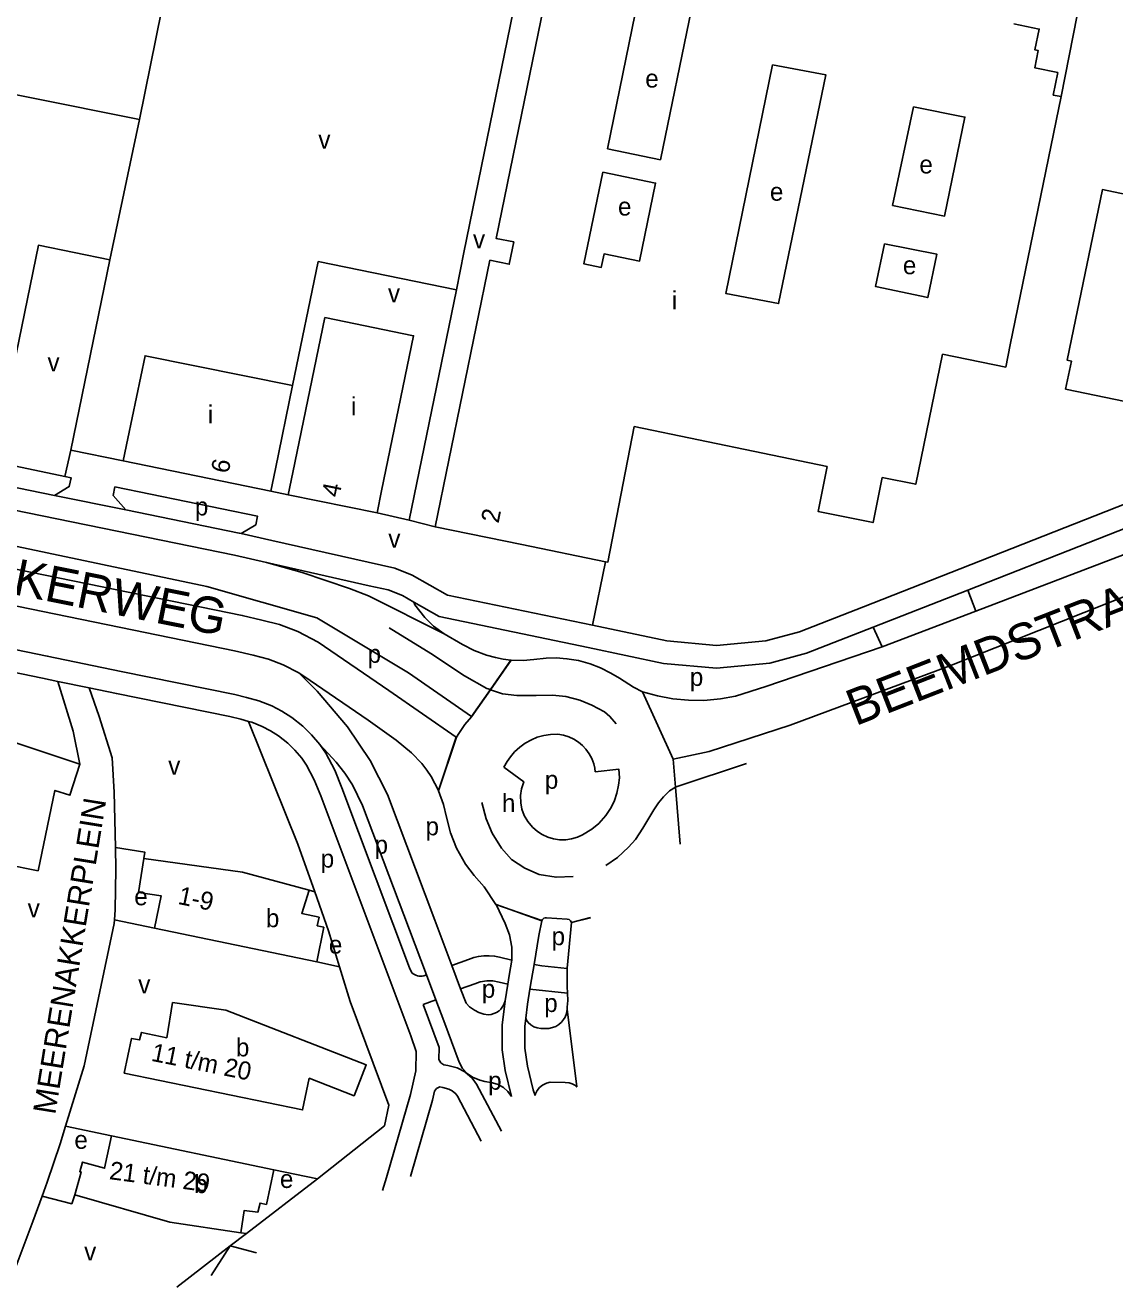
# Model space of a CAD drawing. Extents: x 157699 to 159683, y 381451 to 383293.
# Drawn here: x 158727.7 to 158968.6, y 381916.9 to 382195.6 of the extents above; entities that cross this region are included whole.
import ezdxf

# ---------------------------------------------------------------- set-up
doc = ezdxf.new("R2010")
doc.units = 0
for name, color, linetype in [('BLT_Basislijn', 7, 'Continuous'), ('BLT_Bebouwing', 7, 'Continuous'), ('BLT_Centroide', 7, 'Continuous'), ('BLT_Huisnummer', 7, 'Continuous'), ('BLT_Huisnummer_reeks', 7, 'Continuous'), ('BLT_Onderverdeling_panden', 7, 'Continuous'), ('BLT_Straatnaam', 7, 'Continuous'), ('BLT_Straatnaam_hoofdweg', 7, 'Continuous'), ('BLT_Vlakafsluiter', 7, 'Continuous')]:
    doc.layers.add(name, color=color, linetype=linetype)

msp = doc.modelspace()

# ---------------------------------------------------------------- linework, layer by layer
at = {"layer": 'BLT_Basislijn'}
for p, q in [((158824.7, 382145.3), (158838.81, 382214.57)), ((158823.02, 382137.08), (158824.7, 382145.3)), ((158746.41, 382143.69), (158737.77, 382101.61)), ((158786.8, 382115.91), (158792.49, 382143.37)), ((158792.49, 382143.37), (158823.02, 382137.08)), ((158823.02, 382137.08), (158812.59, 382086.17)), ((158737.77, 382101.61), (158749.36, 382099.29)), ((158720.79, 382099.1), (158736.46, 382095.81)), ((158782, 382092.58), (158785.86, 382091.78)), ((158805.49, 382087.74), (158812.59, 382086.17)), ((158812.59, 382086.17), (158818.34, 382084.7)), ((158936.12, 382070.68), (158937.86, 382066.01)), ((158915.13, 382062.5), (158917.18, 382058.12)), ((158777.07, 382041.68), (158787.99, 382014.51)), ((158790.45, 382004.33), (158791.7, 382003.99)), ((158756.27, 381995.96), (158747.43, 381997.8)), ((158842.96, 381998.23), (158847.5, 381997.99)), ((158792.15, 381988.49), (158797.18, 381987.44)), ((158822.04, 381987.7), (158823.96, 381982.58)), ((158839.29, 381982.51), (158847.6, 381981.63)), ((158799.55, 381979.75), (158808.09, 381956.86)), ((158808.09, 381956.86), (158807.12, 381952.29)), ((158746.77, 381950.06), (158736.65, 381952.18)), ((158807.12, 381952.29), (158792.35, 381940.53)), ((158782.64, 381942.56), (158792.35, 381940.53)), ((158792.35, 381940.53), (158776.63, 381928.47)), ((158776.63, 381928.47), (158773.05, 381925.73)), ((158775.39, 381928.65), (158776.63, 381928.47)), ((158773.05, 381925.73), (158761.2, 381916.64)), ((158773.05, 381925.73), (158778.84, 381924.16))]:
    msp.add_line(p, q, dxfattribs=at)
for points in [[(158898.79, 382234.19), (158899.9, 382239.98), (158900.48, 382240.17), (158965.55, 382226.62), (158965.66, 382225.18), (158956.72, 382179.78)], [(158870.97, 382033.32), (158878.88, 382035.05), (158896.8, 382040.83), (158932.11, 382053.92), (159006.54, 382083.5), (159037.22, 382098.8), (159129.65, 382150.55), (159151.52, 382167.42), (159185.85, 382195.18)], [(159089.91, 382150.02), (159088.85, 382149.22), (159035.79, 382119.61), (159022.43, 382112.48), (159008.87, 382105.74), (158998.17, 382100.87), (158987.38, 382096.23), (158934.38, 382075.37)], [(158544.73, 382122.06), (158548.84, 382121.35), (158552.02, 382120.93), (158587.89, 382116.66), (158592.01, 382115.79), (158605.12, 382111.75), (158611.85, 382110.66), (158626.88, 382108.26), (158640.25, 382105.79), (158773.96, 382078.4), (158781.03, 382076.78)], [(159042.78, 382117.78), (159038.18, 382115.22), (159024.72, 382108.03), (159011.02, 382101.22), (159000.2, 382096.29), (158989.28, 382091.61), (158936.12, 382070.68)], [(158937.86, 382066.01), (158978.78, 382081.64), (158996.94, 382088.82), (159013.88, 382096.22), (159030.16, 382104.6), (159045.4, 382113.11)], [(158672.43, 382104.3), (158734.22, 382091.64)], [(158737.77, 382101.61), (158736.46, 382095.81)], [(158603.4, 382100.5), (158713.37, 382077.85), (158775.69, 382065.11), (158780, 382064.08), (158783.9, 382063.08), (158788, 382061.52), (158792.49, 382059.17)], [(158826.34, 382042.72), (158812.46, 382052.4), (158792.15, 382064.6), (158767.88, 382071.47), (158640.23, 382098.41), (158603.4, 382100.5)], [(158585.04, 382095.72), (158600.84, 382092.86), (158711.76, 382070.02), (158773.96, 382057.3), (158778.07, 382056.31), (158781.48, 382055.44), (158784.72, 382054.21), (158788.18, 382052.4)], [(158736.46, 382095.81), (158737.88, 382095.51), (158737.46, 382093.59), (158734.22, 382091.64)], [(158749.92, 382088.43), (158747.16, 382091.59), (158747.56, 382093.49), (158779.09, 382087.01), (158778.69, 382085.11), (158775.47, 382083.18)], [(158734.22, 382091.64), (158749.92, 382088.43)], [(158749.92, 382088.43), (158775.02, 382083.29), (158775.47, 382083.18)], [(158600.15, 382083.33), (158656.15, 382071.8), (158694.96, 382063.83), (158732.57, 382056.1), (158748.9, 382052.72), (158774.02, 382047.61), (158776.64, 382046.99), (158779.39, 382046.22), (158782.2, 382045.1), (158784.45, 382043.93), (158786.62, 382042.54), (158789.07, 382040.6), (158791.02, 382038.68), (158792.82, 382036.54)], [(158775.47, 382083.18), (158782.26, 382081.63)], [(158853.15, 382062.93), (158821.03, 382069.59), (158813.27, 382074.02), (158809.39, 382075.53), (158782.26, 382081.63)], [(158803.78, 382071.67), (158781.03, 382076.78)], [(158853.15, 382062.93), (158856.02, 382076.98)], [(158934.38, 382075.37), (158913.01, 382067.03)], [(158813.62, 382068.06), (158811.11, 382069.49), (158807.92, 382070.74), (158803.78, 382071.67)], [(158936.12, 382070.68), (158915.13, 382062.5)], [(158852.13, 382058.04), (158819.24, 382064.86), (158813.62, 382068.06)], [(158813.62, 382068.06), (158813.82, 382067.47), (158816.03, 382064.61), (158817.96, 382062.7), (158820.3, 382061.05)], [(158913.01, 382067.03), (158898.86, 382061.48), (158891.46, 382059.48), (158880.51, 382058.47), (158869.56, 382059.46), (158853.15, 382062.93)], [(158917.18, 382058.12), (158937.86, 382066.01)], [(158669.58, 382063.94), (158693.96, 382058.93), (158731.56, 382051.2), (158734.95, 382050.5)], [(158830.54, 382048.7), (158829.77, 382048.96), (158824.83, 382051.76), (158817.41, 382056.65), (158808.18, 382062.32)], [(158915.13, 382062.5), (158900.43, 382056.73), (158892.35, 382054.54), (158880.51, 382053.45), (158868.82, 382054.5), (158852.13, 382058.04)], [(158792.49, 382059.17), (158808.07, 382048.49), (158823.01, 382038.2)], [(158820.3, 382061.05), (158824.35, 382058.69), (158826.94, 382057.38), (158829.7, 382056.33), (158831.66, 382055.79), (158833.37, 382055.44), (158835.1, 382055.2)], [(158864.18, 382048.21), (158867.46, 382047.29), (158870.88, 382046.66), (158874.32, 382046.33), (158877.75, 382046.31), (158881.4, 382046.63), (158884.72, 382047.23), (158891.42, 382049.39), (158917.18, 382058.12)], [(158835.1, 382055.2), (158835.15, 382055.19)], [(158835.15, 382055.19), (158837.78, 382055.15), (158840.13, 382055.36), (158842.85, 382055.67), (158845.05, 382055.7), (158847.47, 382055.53), (158849.99, 382055.11), (158852.61, 382054.39), (158854.85, 382053.53), (158857.17, 382052.37), (158859.05, 382051.21), (158862.18, 382049.24), (158864.18, 382048.21)], [(158739.81, 382032.19), (158738.33, 382039.52), (158734.95, 382050.5)], [(158734.95, 382050.5), (158741.84, 382049.07)], [(158822.04, 381987.7), (158818.26, 381997.73), (158807.81, 382025.49), (158803.95, 382033.03), (158798.97, 382040.45), (158792.24, 382048.38), (158788.18, 382052.4)], [(158788.18, 382052.4), (158790.74, 382050.68), (158803.49, 382041.93), (158809.68, 382037.53), (158813.14, 382034.71), (158815.36, 382032.37), (158816.5, 382030.9), (158817.45, 382029.48), (158819.07, 382026.39)], [(158741.84, 382049.07), (158744.08, 382042.74), (158746.97, 382033.6), (158747.4, 382026), (158747.66, 382013.78)], [(158741.84, 382049.07), (158747.89, 382047.82), (158772.96, 382042.72), (158775.39, 382042.15), (158777.07, 382041.68)], [(158830.59, 382048.68), (158830.54, 382048.7)], [(158858.35, 382041.12), (158856.96, 382042.78), (158855.74, 382043.78), (158853, 382045.25), (158850.32, 382046.33), (158847.23, 382047.15), (158844.28, 382047.48), (158840.63, 382047.37), (158836.41, 382047.43), (158833.24, 382047.78), (158830.59, 382048.68)], [(158823.05, 382038.17), (158823.54, 382039.03), (158824.93, 382041), (158826.39, 382042.69)], [(158826.39, 382042.69), (158826.34, 382042.72)], [(158777.07, 382041.68), (158777.78, 382041.48), (158780.11, 382040.55), (158781.94, 382039.6), (158783.71, 382038.47), (158785.75, 382036.85), (158787.35, 382035.28), (158788.84, 382033.51), (158789.87, 382032.01), (158791.6, 382028.79), (158793.05, 382025.2), (158812.93, 381972.14)], [(158792.82, 382036.54), (158794.15, 382034.62), (158796.13, 382030.91), (158797.71, 382027.02), (158812.63, 381987.18), (158813.19, 381986.1), (158813.46, 381985.88), (158813.76, 381985.69), (158814.05, 381985.55), (158814.43, 381985.43), (158814.74, 381985.37), (158815.16, 381985.34), (158815.47, 381985.36), (158815.85, 381985.43), (158816.4, 381985.64)], [(158816.4, 381985.64), (158812.64, 381995.61), (158802.29, 382023.1), (158800.07, 382027.64), (158798.39, 382030.26), (158796.44, 382032.69), (158792.82, 382036.54)], [(158823.01, 382038.2), (158823.05, 382038.17)], [(158887.15, 382032.39), (158871.82, 382027.31), (158871.47, 382027.1)], [(158819.07, 382026.39), (158819.1, 382026.32)], [(158819.1, 382026.32), (158820.2, 382023.28), (158820.87, 382020.5), (158821.7, 382017.05), (158823.03, 382013.65), (158825.03, 382010.14), (158826.95, 382007.63), (158829.14, 382005.12), (158831.76, 382001.22)], [(158871.47, 382027.1), (158870.15, 382026.31), (158868.83, 382024.96), (158867.72, 382023.65), (158866.69, 382022.15), (158864.21, 382018.08), (158862.59, 382015.6), (158861.05, 382013.85), (158858.62, 382011.6), (158856.03, 382009.83)], [(158828.62, 382023.77), (158829.63, 382020.11), (158830.95, 382016.98), (158832.98, 382013.68), (158835.24, 382011.14), (158838.17, 382009.22), (158841.32, 382007.86), (158845.05, 382007.22), (158848.86, 382007.41)], [(158791.7, 382003.99), (158787.99, 382014.51)], [(158747.66, 382013.78), (158747.76, 382009.03), (158747.63, 382000), (158747.43, 381997.8)], [(158753.9, 382011.33), (158754.12, 382012.79), (158747.66, 382013.78)], [(158797.18, 381987.44), (158794.74, 381995.37), (158791.7, 382003.99)], [(158831.76, 382001.22), (158831.79, 382001.16)], [(158831.79, 382001.16), (158833.83, 381997.01), (158834.78, 381994.46), (158835.28, 381991.79), (158835.3, 381988.92)], [(158747.43, 381997.8), (158747.35, 381997.01), (158740.74, 381965.53), (158736.65, 381952.18)], [(158841.94, 381997.59), (158841.28, 381994.35), (158840.2, 381987.91)], [(158841.95, 381997.64), (158841.94, 381997.59)], [(158842.96, 381998.23), (158842.64, 381998.24), (158842.34, 381998.14), (158842.08, 381997.91), (158841.95, 381997.64)], [(158848.49, 381997.25), (158848.28, 381997.61), (158847.94, 381997.87), (158847.5, 381997.99)], [(158847.5, 381987.03), (158847.5, 381987.11), (158848.49, 381997.19)], [(158848.49, 381997.19), (158848.49, 381997.25)], [(158822.04, 381987.7), (158825.69, 381989.07), (158826.85, 381989.46), (158827.91, 381989.71), (158829.07, 381989.85), (158830.3, 381989.88), (158831.48, 381989.78), (158832.53, 381989.59), (158835.3, 381988.92)], [(158799.55, 381979.75), (158797.18, 381987.44)], [(158835.3, 381988.92), (158834.72, 381985.48), (158834.4, 381983.57)], [(158840.2, 381987.91), (158839.65, 381984.65), (158839.29, 381982.51)], [(158840.2, 381987.91), (158841.9, 381987.64), (158847.5, 381987.03)], [(158847.6, 381981.63), (158847.52, 381983.06), (158847.5, 381987.03)], [(158818.48, 381980.13), (158816.4, 381985.64)], [(158823.96, 381982.58), (158827.1, 381983.69), (158828.31, 381984.11), (158829.74, 381984.34), (158831.09, 381984.31), (158832.45, 381984.04), (158834.4, 381983.57)], [(158834.4, 381983.57), (158833.79, 381979.89)], [(158833.79, 381979.89), (158833.61, 381979.3), (158833.3, 381978.69), (158832.85, 381978.09), (158832.45, 381977.71), (158831.87, 381977.32), (158831.33, 381977.07), (158830.69, 381976.89), (158830.06, 381976.82), (158829.1, 381976.98), (158827.98, 381977.35), (158827.03, 381977.82), (158825.93, 381978.61), (158825.18, 381979.36), (158823.96, 381982.58)], [(158839.29, 381982.51), (158838.74, 381979.19), (158838.37, 381976.04)], [(158847.68, 381980), (158847.6, 381981.63)], [(158815.72, 381979.06), (158818.48, 381980.13)], [(158815.72, 381979.06), (158819.19, 381969.56)], [(158835.19, 381958.78), (158834.41, 381959.85), (158833.41, 381960.73), (158832.29, 381961.37), (158830.99, 381961.79), (158829.34, 381962.08), (158828.18, 381962.39), (158826.62, 381963), (158825.43, 381963.83), (158824.41, 381964.95), (158823.64, 381966.37), (158820.23, 381975.47), (158818.48, 381980.13)], [(158838.37, 381976.04), (158838.55, 381975.64), (158838.93, 381975.1), (158839.5, 381974.56), (158840.17, 381974.15), (158840.87, 381973.91), (158841.67, 381973.81), (158843.49, 381973.81), (158844.31, 381973.98), (158845, 381974.26), (158845.65, 381974.66), (158846.26, 381975.2), (158846.72, 381975.77), (158847.04, 381976.32), (158847.34, 381977.08), (158847.5, 381978.04)], [(158847.5, 381978.04), (158847.51, 381978.49), (158847.68, 381980)], [(158812.93, 381972.14), (158814.17, 381968.73)], [(158814.17, 381968.73), (158814.08, 381964.4), (158812.88, 381959.2), (158807.58, 381940.83), (158806.68, 381938.01)], [(158819.19, 381969.56), (158819.14, 381966.95), (158819.59, 381966.18)], [(158819.59, 381966.18), (158820.22, 381965.78), (158821.11, 381965.63), (158823.2, 381965.06), (158824.86, 381964.17), (158826.54, 381962.84), (158827.51, 381961.47), (158832.99, 381951.1)], [(158840.44, 381958.99), (158840.51, 381959.32), (158840.89, 381960.09), (158841.43, 381960.77), (158842.08, 381961.29), (158842.92, 381961.7), (158843.77, 381961.89), (158847.06, 381961.87), (158847.93, 381961.77), (158848.59, 381961.56), (158849.19, 381961.23), (158849.6, 381960.92), (158849.64, 381960.89)], [(158818.6, 381960.53), (158818.18, 381959.95), (158817.72, 381957.94), (158812.86, 381941.09)], [(158818.6, 381960.53), (158819.38, 381960.86), (158820.01, 381960.75), (158821.34, 381960.38), (158822.11, 381959.97), (158822.87, 381959.37), (158823.24, 381958.85), (158828.51, 381948.87)], [(158736.65, 381952.18), (158735.47, 381948.31), (158732.54, 381939.79), (158731.44, 381936.75)], [(158731.44, 381936.75), (158729.4, 381931.11), (158724.57, 381918.14)], [(158738.68, 381937.05), (158737.99, 381935.04), (158731.44, 381936.75)], [(158768.8, 381919.17), (158773.05, 381925.73)]]:
    msp.add_lwpolyline(points, dxfattribs=at)
msp.add_lwpolyline([(158833.49, 382031.53), (158834.24, 382032.8), (158834.97, 382033.82), (158835.89, 382034.91), (158837.05, 382035.98), (158838.22, 382036.83), (158839.6, 382037.61), (158840.9, 382038.15), (158842.38, 382038.57), (158843.85, 382038.81), (158845.45, 382038.88), (158846.73, 382038.65), (158847.9, 382038.27), (158848.97, 382037.76), (158850, 382037.11), (158850.9, 382036.35), (158851.67, 382035.53), (158852.41, 382034.5), (158852.97, 382033.47), (158853.42, 382032.27), (158853.66, 382031.32), (158853.74, 382030.53), (158858.91, 382031.14), (158859.06, 382029.23), (158858.89, 382027.56), (158858.52, 382025.82), (158857.96, 382024.15), (158857.24, 382022.62), (158856.1, 382020.87), (158854.52, 382019.12), (158852.96, 382017.84), (158850.87, 382016.61), (158849.78, 382016.1), (158848.48, 382015.71), (158847.24, 382015.52), (158845.81, 382015.52), (158844.51, 382015.71), (158843.24, 382016.09), (158841.97, 382016.69), (158840.97, 382017.36), (158839.83, 382018.31), (158838.82, 382019.51), (158838.02, 382020.89), (158837.51, 382022.29), (158837.24, 382023.65), (158837.21, 382025.29), (158837.44, 382026.74), (158837.97, 382028.3)], close=True, dxfattribs=at)
at = {"layer": 'BLT_Bebouwing'}
for p, q in [((158956.72, 382179.78), (158954.93, 382180.14)), ((158752.99, 382174.76), (158751.5, 382167.79)), ((158751.5, 382167.79), (158746.41, 382143.69)), ((158862.36, 382106.84), (158905, 382098.05)), ((158782, 382092.58), (158749.36, 382099.29)), ((158785.86, 382091.78), (158805.49, 382087.74)), ((158818.34, 382084.7), (158837.5, 382080.81)), ((158837.5, 382080.81), (158856.02, 382076.98))]:
    msp.add_line(p, q, dxfattribs=at)
for points in [[(158760.28, 382210.83), (158752.99, 382174.76)], [(158830.4, 382143.62), (158834.71, 382142.74), (158835.71, 382147.65), (158831.82, 382148.44), (158844.22, 382208.94)], [(158954.93, 382180.14), (158955.95, 382185.11), (158950.88, 382186.15), (158951.66, 382189.97), (158950.93, 382190.12), (158951.87, 382194.71), (158946.27, 382195.85)], [(158930.47, 382122.85), (158944.46, 382119.98), (158945.46, 382124.88), (158956.72, 382179.78)], [(159033.59, 382149.04), (159000, 382155.99), (158973.95, 382161.39), (158973.68, 382160.05), (158971.6, 382160.48), (158971.11, 382158.16), (158965.85, 382159.25), (158959, 382126.18), (158958.03, 382121.53), (158958.97, 382121.34), (158957.68, 382115.13), (158975.15, 382111.51), (158976.45, 382117.75), (158977.37, 382117.56), (158981.89, 382139.33), (158995.39, 382136.53), (159029.58, 382129.54)], [(158720.79, 382099.1), (158730.62, 382146.93), (158746.41, 382143.69)], [(158830.4, 382143.62), (158818.34, 382084.7)], [(158805.49, 382087.74), (158806.5, 382092.63), (158813.57, 382126.91), (158793.96, 382130.94), (158786.88, 382096.68), (158785.86, 382091.78)], [(158749.36, 382099.29), (158750.38, 382104.18), (158754.21, 382122.5), (158786.8, 382115.91)], [(158917.18, 382095.6), (158924.57, 382094.09), (158930.47, 382122.85)], [(158786.8, 382115.91), (158783.01, 382097.48), (158782, 382092.58)], [(158856.02, 382076.98), (158856.53, 382076.88), (158862.36, 382106.84)], [(158905, 382098.05), (158903.01, 382088.05), (158915.13, 382085.61), (158917.18, 382095.6)], [(158689.74, 382042.67), (158725.62, 382036.91), (158739.81, 382032.19)], [(158739.81, 382032.19), (158737.6, 382025.35), (158734.29, 382026.43), (158730.57, 382008.65), (158723.26, 382010.13)], [(158753.9, 382011.33), (158752.75, 382003.84), (158757.74, 382003.13), (158756.27, 381995.96)], [(158790.45, 382004.33), (158775.75, 382008.34), (158753.9, 382011.33)], [(158792.69, 381998.43), (158788.85, 381999.23), (158790.45, 382004.33)], [(158793.75, 381996.17), (158792.28, 381996.48), (158792.69, 381998.43)], [(158756.27, 381995.96), (158792.15, 381988.49)], [(158792.15, 381988.49), (158793.75, 381996.17)], [(158760.27, 381979.51), (158772.07, 381977.83), (158803.09, 381965.73), (158800.43, 381958.93), (158790.49, 381962.78), (158789.03, 381955.77), (158749.6, 381963.93), (158751.21, 381971.6), (158753.01, 381971.25), (158753.39, 381972.93), (158759, 381971.74), (158760.27, 381979.51)], [(158738.68, 381937.05), (158740.11, 381942.03), (158739.78, 381942.13), (158740.41, 381944.25), (158745.27, 381942.9), (158746.77, 381950.06)], [(158746.77, 381950.06), (158782.64, 381942.56)], [(158782.64, 381942.56), (158781.03, 381934.89), (158779.65, 381935.18), (158779.1, 381933.15), (158776.12, 381933.56), (158775.39, 381928.65)], [(158775.39, 381928.65), (158759.69, 381930.94), (158738.68, 381937.05)]]:
    msp.add_lwpolyline(points, dxfattribs=at)
for points in [[(158863.2, 382201.49), (158874.97, 382199.14), (158868.14, 382165.84), (158856.44, 382168.27)], [(158892.91, 382186.83), (158904.67, 382184.6), (158894.27, 382134.03), (158882.59, 382136.28)], [(158924.07, 382177.51), (158935.45, 382175.27), (158930.93, 382153.36), (158919.44, 382155.73)], [(158855.38, 382163.05), (158867.08, 382160.67), (158863.54, 382143.44), (158855.66, 382145.01), (158855.05, 382142.01), (158851.22, 382142.8)], [(158917.66, 382147.23), (158929.2, 382144.96), (158927.23, 382135.37), (158915.67, 382137.82)]]:
    msp.add_lwpolyline(points, close=True, dxfattribs=at)
at = {"layer": 'BLT_Onderverdeling_panden'}
for p, q in [((158702.89, 382184.73), (158728.38, 382179.66)), ((158728.38, 382179.66), (158752.99, 382174.76))]:
    msp.add_line(p, q, dxfattribs=at)
at = {"layer": 'BLT_Vlakafsluiter'}
for p, q in [((158830.54, 382048.7), (158835.1, 382055.2)), ((158830.59, 382048.68), (158835.15, 382055.19)), ((158826.34, 382042.72), (158830.54, 382048.7)), ((158826.39, 382042.69), (158830.59, 382048.68)), ((158870.97, 382033.32), (158864.18, 382048.21)), ((158823.01, 382038.2), (158819.07, 382026.39)), ((158823.05, 382038.17), (158819.1, 382026.32)), ((158871.47, 382027.1), (158870.97, 382033.32)), ((158872.47, 382014.55), (158871.47, 382027.1)), ((158841.95, 381997.64), (158831.76, 382001.22)), ((158841.94, 381997.59), (158831.79, 382001.16)), ((158848.49, 381997.25), (158852.66, 381998.3)), ((158848.49, 381997.19), (158852.67, 381998.25))]:
    msp.add_line(p, q, dxfattribs=at)
for points in [[(158781.03, 382076.78), (158788.96, 382074.59), (158799.37, 382071.04), (158803.57, 382069.41)], [(158803.57, 382069.41), (158820.3, 382061.05)], [(158833.79, 381979.89), (158833.16, 381974.49), (158833.14, 381969.06), (158833.83, 381964.51), (158835.19, 381958.78)], [(158849.64, 381960.89), (158847.5, 381978.04)], [(158838.37, 381976.04), (158838.15, 381974.19), (158838.14, 381969.43), (158838.74, 381965.47), (158839.99, 381960.21), (158840.44, 381958.99)]]:
    msp.add_lwpolyline(points, dxfattribs=at)

# ---------------------------------------------------------------- texts
at = {"layer": 'BLT_Centroide'}
for s, p in [('e', (158864.78, 382181.79)), ('v', (158792.52, 382168.27)), ('e', (158925.38, 382162.8)), ('e', (158892.34, 382156.77)), ('e', (158858.76, 382153.49)), ('v', (158826.7, 382146.26)), ('e', (158921.73, 382140.52)), ('v', (158807.91, 382134.34)), ('i', (158870.66, 382132.77)), ('v', (158732.65, 382119.09)), ('i', (158768.08, 382107.53)), ('i', (158799.72, 382109.34)), ('p', (158765.22, 382087.2)), ('v', (158807.98, 382080.07)), ('p', (158803.4, 382054.62)), ('p', (158874.64, 382049.51)), ('v', (158759.33, 382029.91)), ('p', (158842.58, 382026.78)), ('h', (158833.1, 382021.61)), ('p', (158816.21, 382016.49)), ('p', (158804.94, 382012.43)), ('p', (158793.04, 382009.35)), ('e', (158751.82, 382001.02)), ('v', (158728.27, 381998.35)), ('b', (158780.92, 381996.18)), ('p', (158844.08, 381992.19)), ('e', (158794.84, 381990.33)), ('v', (158752.71, 381981.55)), ('p', (158828.65, 381980.57)), ('p', (158842.45, 381977.43)), ('b', (158774.29, 381967.62)), ('p', (158830.05, 381960.25)), ('e', (158738.58, 381947.19)), ('b', (158765.06, 381937.39)), ('e', (158784.02, 381938.53)), ('v', (158740.75, 381922.5))]:
    msp.add_text(s, height=4, dxfattribs=at).set_placement(p)
at = {"layer": 'BLT_Huisnummer'}
for s, rotation, p in [('6', 78.3879, (158772.63, 382096.32)), ('4', 78.343, (158797.12, 382091.02))]:
    msp.add_text(s, height=4, rotation=rotation, dxfattribs=at).set_placement(p)
at = {"layer": 'BLT_Huisnummer_reeks'}
for s, rotation, p in [('2', 78.979, (158832.35, 382085.33)), ('1-9', 348.1965, (158761.3, 382001.35)), ('11 t/m 20', 348.5816, (158755.38, 381966.67)), ('21 t/m 29', 352.4454, (158746.15, 381940.5))]:
    msp.add_text(s, height=4, rotation=rotation, dxfattribs=at).set_placement(p)
at = {"layer": 'BLT_Straatnaam'}
msp.add_text('MEERENAKKERPLEIN', height=5, rotation=80.7939, dxfattribs=at).set_placement((158734.35, 381954.6))
at = {"layer": 'BLT_Straatnaam_hoofdweg'}
for s, rotation, p in [('MEERENAKKERWEG', 348.7122, (158665.82, 382081.59)), ('BEEMDSTRAAT', 21.3388, (158911.24, 382040.59))]:
    msp.add_text(s, height=8, rotation=rotation, dxfattribs=at).set_placement(p)

doc.saveas('drawing.dxf')
